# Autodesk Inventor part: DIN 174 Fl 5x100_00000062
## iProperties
Created: 2006-03
Part Number: DIN 174 Fl 5x100_00000062
Material: Default
Document SubType Name: Modeling
Designer: Carlo
Stock Number: DIN 174 Fl 5x100
Mass: 881.349 g
Surface Area: 3712.08 cm^2
Volume: 881.349 cm^3
Density: 1 g/cm^3
G_L: 1762.896 mm
G_W: 5.000 mm
G_H: 100.000 mm
AFG_Item: 100 x 5
CSToolsMass: 1.0
CSToolsVolume: 881349.0
CSToolsArea: 3712.0
Author: Carlo
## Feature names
1. AFG_Detailed_DIN 174 Fl 5x100_00000062 [Extrusion]
2. AFG_Simplified_DIN 174 Fl 5x100_00000062 [Extrusion]
3. AFG_StartExtrusion_1 [Extrusion]
4. AFG_StartExtrusion_2 [Extrusion]
5. AFG_EndExtrusion_1 [Extrusion]
6. AFG_EndExtrusion_2 [Extrusion]
